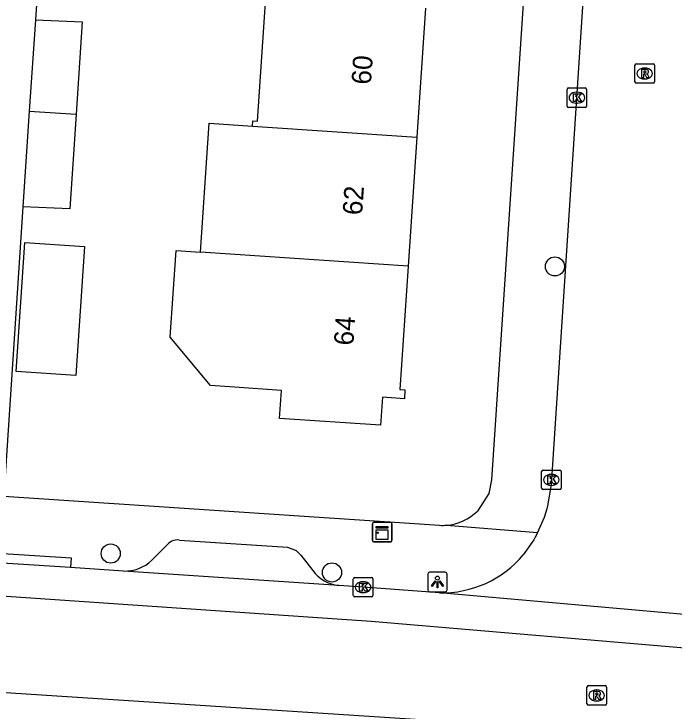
# Model space of a CAD drawing. Extents: x 161848 to 162726, y 385382 to 386521.
# Drawn here: x 162101.38 to 162135.16, y 385740.75 to 385776.42 of the extents above; entities that cross this region are included whole.
import ezdxf

# ---------------------------------------------------------------- set-up
doc = ezdxf.new("R2010")
doc.units = 0
for name, color, linetype in [('IMGEO_Boom', 7, 'Continuous'), ('IMGEO_Kast', 7, 'Continuous'), ('IMGEO_Kolk', 7, 'Continuous'), ('IMGEO_Lichtpunt', 7, 'Continuous'), ('IMGEO_Pand', 7, 'Continuous'), ('IMGEO_Pand_nummerreeks', 7, 'Continuous'), ('IMGEO_Rijbaan_lokaal_gesloten', 7, 'Continuous'), ('IMGEO_Rijbaan_lokaal_open', 7, 'Continuous'), ('IMGEO_Rioolput', 7, 'Continuous'), ('IMGEO_Voetpad_open', 7, 'Continuous')]:
    doc.layers.add(name, color=color, linetype=linetype)

msp = doc.modelspace()

# ---------------------------------------------------------------- linework, layer by layer
at = {"layer": 'IMGEO_Boom'}
for centre in [(162129.06, 385763.502), (162106.328, 385748.811), (162117.651, 385747.842)]:
    msp.add_circle(centre, 0.489, dxfattribs=at)
at = {"layer": 'IMGEO_Kast'}
for p, q in [((162119.716, 385749.483), (162119.716, 385750.324)), ((162119.716, 385750.324), (162119.716, 385749.483)), ((162119.791, 385750.408), (162120.632, 385750.408)), ((162120.632, 385750.408), (162119.791, 385750.408)), ((162120.716, 385750.333), (162120.716, 385749.492)), ((162120.716, 385749.492), (162120.716, 385750.333)), ((162120.641, 385749.408), (162119.8, 385749.408)), ((162119.8, 385749.408), (162120.641, 385749.408))]:
    msp.add_line(p, q, dxfattribs=at)
for points in [[(162119.911, 385750.198), (162120.511, 385750.198), (162120.511, 385750.113), (162119.911, 385750.113), (162119.911, 385750.198)], [(162119.911, 385750.023), (162120.511, 385750.023), (162120.511, 385749.534), (162119.911, 385749.534), (162119.911, 385750.023)]]:
    msp.add_lwpolyline(points, dxfattribs=at)
msp.add_circle((162119.995, 385749.872), 0.0377, dxfattribs=at)
for centre, start, end in [((162119.794, 385750.33), 92.4484, 184.2845), ((162119.794, 385750.33), 92.4484, 184.2845), ((162120.638, 385750.33), 2.4484, 94.2845), ((162120.638, 385750.33), 2.4484, 94.2845), ((162120.638, 385749.486), 272.4484, 4.2845), ((162120.638, 385749.486), 272.4484, 4.2845), ((162119.794, 385749.486), 182.4484, 274.2845), ((162119.794, 385749.486), 182.4484, 274.2845)]:
    msp.add_arc(centre, 0.0779, start, end, dxfattribs=at)
at = {"layer": 'IMGEO_Kolk'}
for p, q in [((162129.681, 385771.711), (162129.681, 385772.563)), ((162129.756, 385772.637), (162130.608, 385772.637)), ((162130.169, 385772.417), (162130.194, 385772.417)), ((162130.682, 385772.563), (162130.682, 385771.711)), ((162130.608, 385771.637), (162129.756, 385771.637)), ((162130.192, 385771.857), (162130.167, 385771.857)), ((162128.452, 385753.08), (162129.304, 385753.08)), ((162128.377, 385752.154), (162128.377, 385753.006)), ((162128.865, 385752.86), (162128.89, 385752.86)), ((162129.378, 385753.006), (162129.378, 385752.154)), ((162129.304, 385752.08), (162128.452, 385752.08)), ((162128.888, 385752.3), (162128.863, 385752.3)), ((162118.743, 385746.663), (162118.743, 385747.515)), ((162118.818, 385747.589), (162119.67, 385747.589)), ((162119.231, 385747.369), (162119.256, 385747.369)), ((162119.744, 385747.515), (162119.744, 385746.663)), ((162119.254, 385746.809), (162119.229, 385746.809)), ((162119.67, 385746.589), (162118.818, 385746.589))]:
    msp.add_line(p, q, dxfattribs=at)
for points in [[(162129.681, 385771.711), (162129.681, 385772.563)], [(162129.756, 385772.637), (162130.608, 385772.637)], [(162130.002, 385772.337), (162130.125, 385772.337), (162130.125, 385772.186), (162130.255, 385772.337), (162130.419, 385772.337), (162130.273, 385772.186), (162130.426, 385771.937), (162130.274, 385771.937), (162130.189, 385772.101), (162130.125, 385772.034), (162130.125, 385771.937), (162130.002, 385771.937), (162130.002, 385772.337)], [(162130.682, 385772.563), (162130.682, 385771.711)], [(162130.608, 385771.637), (162129.756, 385771.637)], [(162128.452, 385753.08), (162129.304, 385753.08)], [(162128.377, 385752.154), (162128.377, 385753.006)], [(162128.698, 385752.78), (162128.821, 385752.78), (162128.821, 385752.629), (162128.951, 385752.78), (162129.115, 385752.78), (162128.969, 385752.629), (162129.122, 385752.38), (162128.97, 385752.38), (162128.885, 385752.544), (162128.821, 385752.477), (162128.821, 385752.38), (162128.698, 385752.38), (162128.698, 385752.78)], [(162129.378, 385753.006), (162129.378, 385752.154)], [(162129.304, 385752.08), (162128.452, 385752.08)], [(162118.743, 385746.663), (162118.743, 385747.515)], [(162118.818, 385747.589), (162119.67, 385747.589)], [(162119.744, 385747.515), (162119.744, 385746.663)], [(162119.064, 385747.289), (162119.187, 385747.289), (162119.187, 385747.138), (162119.317, 385747.289), (162119.481, 385747.289), (162119.335, 385747.138), (162119.488, 385746.889), (162119.336, 385746.889), (162119.251, 385747.053), (162119.187, 385746.986), (162119.187, 385746.889), (162119.064, 385746.889), (162119.064, 385747.289)], [(162119.67, 385746.589), (162118.818, 385746.589)]]:
    msp.add_lwpolyline(points, dxfattribs=at)
for centre, start, end in [((162129.758, 385772.561), 91.552, 178.448), ((162129.758, 385772.561), 91.552, 178.448), ((162130.606, 385772.561), 1.552, 88.448), ((162130.606, 385772.561), 1.552, 88.448), ((162129.758, 385771.713), 181.552, 268.448), ((162129.758, 385771.713), 181.552, 268.448), ((162130.606, 385771.713), 271.552, 358.448), ((162130.606, 385771.713), 271.552, 358.448), ((162128.454, 385753.004), 91.552, 178.448), ((162128.454, 385753.004), 91.552, 178.448), ((162129.302, 385753.004), 1.552, 88.448), ((162129.302, 385753.004), 1.552, 88.448), ((162128.454, 385752.156), 181.552, 268.448), ((162128.454, 385752.156), 181.552, 268.448), ((162129.302, 385752.156), 271.552, 358.448), ((162129.302, 385752.156), 271.552, 358.448), ((162118.82, 385747.513), 91.552, 178.448), ((162118.82, 385747.513), 91.552, 178.448), ((162119.668, 385747.513), 1.552, 88.448), ((162119.668, 385747.513), 1.552, 88.448), ((162118.82, 385746.665), 181.552, 268.448), ((162118.82, 385746.665), 181.552, 268.448), ((162119.668, 385746.665), 271.552, 358.448), ((162119.668, 385746.665), 271.552, 358.448)]:
    msp.add_arc(centre, 0.0765, start, end, dxfattribs=at)
for centre, major_axis, ratio, start_param, end_param in [((162130.168, 385772.137), (-0.387, 0.002), 0.722429, 4.712389, 7.853982), ((162130.193, 385772.137), (-0.39, 0.002), 0.717154, 1.570796, 4.712389), ((162128.864, 385752.58), (-0.387, 0.002), 0.722429, 4.712389, 7.853982), ((162128.889, 385752.58), (-0.39, 0.002), 0.717154, 1.570796, 4.712389), ((162119.23, 385747.089), (-0.387, 0.002), 0.722429, 4.712389, 7.853982), ((162119.255, 385747.089), (-0.39, 0.002), 0.717154, 1.570796, 4.712389)]:
    msp.add_ellipse(centre, major_axis=major_axis, ratio=ratio, start_param=start_param, end_param=end_param, dxfattribs=at)
at = {"layer": 'IMGEO_Lichtpunt'}
for p, q in [((162122.549, 385747.755), (162122.549, 385746.948)), ((162122.549, 385747.755), (162122.549, 385746.948)), ((162123.451, 385747.85), (162122.643, 385747.85)), ((162123.451, 385747.85), (162122.643, 385747.85)), ((162123.545, 385746.948), (162123.545, 385747.755)), ((162123.545, 385746.948), (162123.545, 385747.755)), ((162122.643, 385746.854), (162123.451, 385746.854)), ((162122.643, 385746.854), (162123.451, 385746.854))]:
    msp.add_line(p, q, dxfattribs=at)
for points in [[(162122.923, 385747.419), (162122.962, 385747.391), (162122.774, 385747.129), (162122.736, 385747.156), (162122.923, 385747.419)], [(162123.025, 385747.371), (162123.072, 385747.371), (162123.072, 385747.049), (162123.025, 385747.049), (162123.025, 385747.371)], [(162123.135, 385747.391), (162123.173, 385747.418), (162123.36, 385747.156), (162123.321, 385747.128), (162123.135, 385747.391)]]:
    msp.add_lwpolyline(points, dxfattribs=at)
msp.add_circle((162123.048, 385747.553), 0.0994, dxfattribs=at)
for centre, start, end in [((162122.643, 385747.755), 90, 180), ((162122.643, 385747.755), 90, 180), ((162123.451, 385747.755), 0, 90), ((162123.451, 385747.755), 0, 90), ((162122.643, 385746.948), 180, 270), ((162122.643, 385746.948), 180, 270), ((162123.451, 385746.948), 270, 0), ((162123.451, 385746.948), 270, 360)]:
    msp.add_arc(centre, 0.0946, start, end, dxfattribs=at)
at = {"layer": 'IMGEO_Pand'}
for points in [[(162113.579, 385770.683), (162113.597, 385770.946), (162113.836, 385770.929), (162114.264, 385777.274)], [(162122.432, 385776.723), (162121.986, 385770.116)], [(162102.474, 385776.123), (162102.161, 385771.453)], [(162102.474, 385776.123), (162104.871, 385776.017), (162104.554, 385771.291)], [(162102.161, 385771.453), (162101.833, 385766.551)], [(162104.554, 385771.291), (162104.23, 385766.445), (162101.833, 385766.551)], [(162102.161, 385771.453), (162104.554, 385771.291)], [(162110.924, 385764.225), (162111.37, 385770.832), (162113.579, 385770.683)], [(162113.579, 385770.683), (162121.986, 385770.116)], [(162121.986, 385770.116), (162121.541, 385763.509)], [(162104.546, 385757.925), (162101.484, 385758.13), (162101.926, 385764.732), (162104.988, 385764.527), (162104.546, 385757.925)], [(162121.541, 385763.509), (162121.115, 385757.199), (162121.384, 385757.181), (162121.354, 385756.735), (162120.237, 385756.81), (162120.141, 385755.375), (162114.973, 385755.721), (162115.069, 385757.159), (162112.669, 385757.321), (162111.438, 385757.405), (162109.37, 385759.88), (162109.67, 385764.32), (162110.924, 385764.225)], [(162121.541, 385763.509), (162110.924, 385764.225)]]:
    msp.add_lwpolyline(points, dxfattribs=at)
at = {"layer": 'IMGEO_Rijbaan_lokaal_gesloten'}
for points in [[(162041.237, 385750.595), (162081.802, 385747.948), (162119.648, 385745.356), (162154.961, 385742.34), (162177.493, 385740.169), (162184.046, 385739.537), (162186.362, 385739.314)], [(162104.27, 385748.089), (162100.507, 385748.337)], [(162106.983, 385747.914), (162104.27, 385748.089)], [(162117.993, 385747.172), (162106.983, 385747.914)], [(162123.16, 385746.805), (162119.24, 385747.088), (162117.993, 385747.172)], [(162140.503, 385745.272), (162123.16, 385746.805)], [(162186.826, 385734.287), (162184.65, 385734.497), (162177.9, 385735.148), (162157.058, 385737.16), (162131.864, 385739.672), (162089.667, 385742.424), (162064.724, 385744.182), (162040.807, 385745.812)]]:
    msp.add_lwpolyline(points, dxfattribs=at)
at = {"layer": 'IMGEO_Rijbaan_lokaal_open'}
for points in [[(162131.97, 385799.695), (162128.863, 385752.339), (162128.687, 385751.25), (162128.645, 385751.095), (162128.505, 385750.663), (162128.216, 385750), (162128.164, 385749.886)], [(162128.164, 385749.886), (162128.109, 385749.773), (162128.043, 385749.646), (162127.974, 385749.52), (162127.442, 385748.75)]]:
    msp.add_lwpolyline(points, dxfattribs=at)
msp.add_arc((162123.303, 385752.176), 5.373, 268.472, 320.3857, dxfattribs=at)
at = {"layer": 'IMGEO_Rioolput'}
for p, q in [((162133.153, 385772.948), (162133.153, 385773.8)), ((162133.228, 385773.874), (162134.08, 385773.874)), ((162134.154, 385773.8), (162134.154, 385772.948)), ((162133.641, 385773.654), (162133.666, 385773.654)), ((162133.664, 385773.094), (162133.639, 385773.094)), ((162134.08, 385772.874), (162133.228, 385772.874)), ((162130.773, 385742.05), (162131.625, 385742.05)), ((162130.698, 385741.124), (162130.698, 385741.976)), ((162131.186, 385741.83), (162131.211, 385741.83)), ((162131.699, 385741.976), (162131.699, 385741.124)), ((162131.625, 385741.05), (162130.773, 385741.05)), ((162131.209, 385741.27), (162131.184, 385741.27))]:
    msp.add_line(p, q, dxfattribs=at)
for points in [[(162133.153, 385772.948), (162133.153, 385773.8)], [(162133.228, 385773.874), (162134.08, 385773.874)], [(162134.154, 385773.8), (162134.154, 385772.948)], [(162133.742, 385773.572), (162133.49, 385773.574), (162133.49, 385773.174)], [(162133.668, 385773.493), (162133.614, 385773.493), (162133.614, 385773.412)], [(162133.614, 385773.412), (162133.666, 385773.412)], [(162133.49, 385773.174), (162133.614, 385773.174), (162133.614, 385773.336), (162133.625, 385773.336)], [(162133.672, 385773.307), (162133.743, 385773.174), (162133.883, 385773.174), (162133.818, 385773.3)], [(162134.08, 385772.874), (162133.228, 385772.874)], [(162130.773, 385742.05), (162131.625, 385742.05)], [(162130.698, 385741.124), (162130.698, 385741.976)], [(162131.287, 385741.748), (162131.035, 385741.75), (162131.035, 385741.35)], [(162131.213, 385741.669), (162131.159, 385741.669), (162131.159, 385741.588)], [(162131.699, 385741.976), (162131.699, 385741.124)], [(162131.035, 385741.35), (162131.159, 385741.35), (162131.159, 385741.512), (162131.17, 385741.512)], [(162131.159, 385741.588), (162131.211, 385741.588)], [(162131.217, 385741.483), (162131.288, 385741.35), (162131.428, 385741.35), (162131.363, 385741.476)], [(162131.625, 385741.05), (162130.773, 385741.05)]]:
    msp.add_lwpolyline(points, dxfattribs=at)
for centre, radius, start, end in [((162133.23, 385773.798), 0.0765, 91.552, 178.448), ((162133.23, 385773.798), 0.0765, 91.552, 178.448), ((162134.078, 385773.798), 0.0765, 1.552, 88.448), ((162134.078, 385773.798), 0.0765, 1.552, 88.448), ((162133.65, 385773.601), 0.19, 274.7715, 282.9687), ((162133.674, 385773.397), 0.0964, 77.0061, 93.1865), ((162133.688, 385773.454), 0.0378, 276.6634, 79.6772), ((162133.741, 385773.462), 0.109, 350.3612, 89.416), ((162133.739, 385773.462), 0.112, 277.5842, 350.9817), ((162133.624, 385773.283), 0.0533, 26.0293, 88.6989), ((162133.723, 385773.247), 0.108, 29.5134, 73.7905), ((162133.23, 385772.95), 0.0765, 181.552, 268.448), ((162133.23, 385772.95), 0.0765, 181.552, 268.448), ((162134.078, 385772.95), 0.0765, 271.552, 358.448), ((162134.078, 385772.95), 0.0765, 271.552, 358.448), ((162130.775, 385741.974), 0.0765, 91.552, 178.448), ((162130.775, 385741.974), 0.0765, 91.552, 178.448), ((162131.623, 385741.974), 0.0765, 1.552, 88.448), ((162131.623, 385741.974), 0.0765, 1.552, 88.448), ((162131.219, 385741.573), 0.0964, 77.0061, 93.1865), ((162131.233, 385741.63), 0.0378, 276.6634, 79.6772), ((162131.286, 385741.638), 0.109, 350.3612, 89.416), ((162131.169, 385741.459), 0.0533, 26.0293, 88.6989), ((162131.195, 385741.777), 0.19, 274.7715, 282.9687), ((162131.284, 385741.638), 0.112, 277.5842, 350.9817), ((162131.268, 385741.423), 0.108, 29.5134, 73.7905), ((162130.775, 385741.126), 0.0765, 181.552, 268.448), ((162130.775, 385741.126), 0.0765, 181.552, 268.448), ((162131.623, 385741.126), 0.0765, 271.552, 358.448), ((162131.623, 385741.126), 0.0765, 271.552, 358.448)]:
    msp.add_arc(centre, radius, start, end, dxfattribs=at)
for centre, major_axis, ratio, start_param, end_param in [((162133.64, 385773.374), (-0.387, 0.002), 0.722429, 4.712389, 7.853982), ((162133.665, 385773.374), (-0.39, 0.002), 0.717154, 1.570796, 4.712389), ((162131.185, 385741.55), (-0.387, 0.002), 0.722429, 4.712389, 7.853982), ((162131.21, 385741.55), (-0.39, 0.002), 0.717154, 1.570796, 4.712389)]:
    msp.add_ellipse(centre, major_axis=major_axis, ratio=ratio, start_param=start_param, end_param=end_param, dxfattribs=at)
at = {"layer": 'IMGEO_Voetpad_open'}
for points in [[(162128.766, 385796.974), (162125.822, 385752.589), (162125.671, 385751.883), (162125.095, 385750.985)], [(162102.716, 385779.735), (162102.474, 385776.123)], [(162101.833, 385766.551), (162100.851, 385751.751)], [(162100.851, 385751.751), (162123.16, 385750.258)], [(162123.516, 385750.26), (162128.164, 385749.886)], [(162109.848, 385749.503), (162115.367, 385749.131), (162115.817, 385748.964), (162116.051, 385748.726), (162116.668, 385747.945)], [(162108.432, 385748.469), (162109.144, 385749.181)], [(162100.507, 385748.337), (162100.54, 385748.835), (162104.302, 385748.587), (162104.27, 385748.089)]]:
    msp.add_lwpolyline(points, dxfattribs=at)
for centre, radius, start, end in [((162123.33, 385752.748), 2.495, 274.282, 315.0426), ((162123.325, 385752.519), 2.267, 265.8179, 274.8258), ((162109.776, 385748.73), 0.776, 84.6747, 144.4827), ((162107.04, 385749.935), 2.022, 268.3912, 313.5248), ((162118.199, 385749.048), 1.887, 215.7552, 263.7265)]:
    msp.add_arc(centre, radius, start, end, dxfattribs=at)

# ---------------------------------------------------------------- texts
at = {"layer": 'IMGEO_Pand_nummerreeks'}
for s, p in [('60', (162119.641, 385772.785)), ('62', (162119.19, 385766.106)), ('64', (162118.741, 385759.435))]:
    msp.add_text(s, height=1, rotation=86.1402, dxfattribs=at).set_placement(p)

doc.saveas('drawing.dxf')
